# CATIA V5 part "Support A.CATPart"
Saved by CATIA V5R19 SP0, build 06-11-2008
Part number: Support A
Bounding box of the stored display mesh (mm): x -127 to 127, y -305.791 to 314.01, z -1400.007 to -1200.007
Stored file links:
  G:\EU_thinkMotion\CFAO_2010\MMS_groupe3\MMS_groupe3\rdalborgo\rdalborgo\Support A.CATPart
  G:\EU_thinkMotion\CFAO_2010\MMS_groupe3\MMS_groupe3\rdalborgo\rdalborgo\rdalborgo.CATProduct
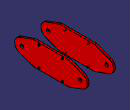
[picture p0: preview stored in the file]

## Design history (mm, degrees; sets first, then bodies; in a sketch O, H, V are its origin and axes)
External parameters (linked from other documents)
  External.entraxe = 500 mm
  `External.Largeur bielle` = 210 mm
Set1
  Plane1: linked copy from another document
  Point1 "C bielle": linked copy from another document
  Point2 "D bielle": linked copy from another document
  Line1: linked copy from another document
  Point3 "Axe sabot": linked copy from another document
  Plane2 to Plane4: linked copy from another document
Body1 (main body)
  Sketch1 on Plane1, origin (0, 0, 0), H (0, 1, 0), V (0, 0, 1)
    arc A1 centre (254.0096, -1300.0067) radius 60 from (314.0096, -1300.0067) to (274.4283, -1243.588) ccw
    point P1 (254.0096, -1300.0067)
    reference projected point E1 (254.0096, -1300.0067) from Point1
    point P2 (-245.9904, -1300.0067)
    reference projected point E2 (-245.9904, -1300.0067) from Point2
    point P3 (-145.9904, -1200.0067)
    line L1 (-145.9904, -1200.0067) -> (154.0096, -1200.0067)
    line L2 (154.0096, -1400.0067) -> (-145.9904, -1400.0067)
    point P4 (154.0096, -1200.0067)
    point P5 (154.0096, -1400.0067)
    reference projected point E3 (4.0096, -1300.0067) from Point3
    line L3 (154.0096, -1200.0067) -> (274.4283, -1243.588)
    line L4 (154.0096, -1400.0067) -> (274.4283, -1356.4254)
    point P8 (274.4283, -1356.4254)
    line L5 (-145.9904, -1400.0067) -> (-266.4092, -1356.4254)
    line L6 (-145.9904, -1200.0067) -> (-266.4092, -1243.588)
    reference projected line E4 (4.0096, -830) -> (4.0096, -1500) from Line1
    reference projected line E5 (4.0096, -830) -> (4.0096, -1500) from Line1
    arc A2 centre (254.0096, -1300.0067) radius 60 from (274.4283, -1356.4254) to (314.0096, -1300.0067) ccw
    point P11 (314.0096, -1300.0067)
    point P12 (314.0096, -1300.0067)
    arc A3 centre (-245.9904, -1300.0067) radius 60 from (-266.4092, -1243.588) to (-266.4092, -1356.4254) ccw
    circle A4 centre (-245.9904, -1300.0067) radius 15
    point P13 (-245.9904, -1300.0067)
    circle A5 centre (254.0096, -1300.0067) radius 15
    point P14 (254.0096, -1300.0067)
    reference projected point E6 (-245.9904, -1300.0067) from Point2
    reference projected point E7 (254.0096, -1300.0067) from Point1
    radius A1 = 60
    distance L1 L2 = 200
    distance L1 E3 = 100
    distance P4 P3 = 300 {= External.entraxe -200mm}
    distance P4 E4 = 150 {= (External.entraxe -200mm)/2}
    length L2 = 300 {= External.entraxe -200mm}
    distance P5 E5 = 150 {= (External.entraxe -200mm)/2}
    radius A3 = 60
    radius A4 = 15
    radius A5 = 15
    coincidence: P1 E1, P2 E2, P8 A1, A1 A2, P13 E6, P14 E7, P11 P12
    horizontal: L1 H, L2 H
    tangency: L3 A1, L4 A1, A3 L6, A3 L5
  Pad1: profile Sketch1, direction (1, 0, 0), length 120 {= `External.Largeur bielle`/2 +15mm}, opposite side length -105 {= -`External.Largeur bielle` /2}
  Sketch2 on end face of Pad1, origin (120, -139.9474, -1261.6138), H (0, 1, 0), V (0, 0, 1)
    point P1 (43.9569, 46.6071)
    reference projected line E1 (143.9569, 431.6138) -> (143.9569, -238.3862) from Line1
    reference intersected line E2 through (0, -38.3929) direction (-1, 0) from Plane2
    distance P1 E1 = 100
    distance P1 E2 = 85
  Hole1: placed by Sketch2, at (120, -95.9904, -1215.0067) direction (-1, 0, 0), diameter 10, through (limit type 6)
  RectPattern1: of Hole1, direction 1 instances 2, spacing 200, along Plane3, direction 2 instances 2, spacing 170, along Plane3 reversed
  Pad2: profile Sketch1, direction (-1, 0, 0), length 120 {= `External.Largeur bielle` /2+15mm}, opposite side length -105 {= -`External.Largeur bielle` /2}
  Sketch3 on end face of Pad2, origin (-120, -3.1951, -1265.3574), H (0, 1, 0), V (0, 0, -1)
    point P1 (107.2047, -50.3507)
    reference intersected line E1 through (7.2047, 0) direction (0, 1) from Plane4
    reference intersected line E2 through (0, 34.6493) direction (1, 0) from Plane2
    distance P1 E1 = 100
    distance P1 E2 = 85
  Hole2: placed by Sketch3, at (-120, 104.0096, -1215.0067) direction (1, 0, 0), diameter 10, through (limit type 6)
  RectPattern2: of Hole2, direction 1 instances 2, spacing 200, along Plane1 reversed, direction 2 instances 2, spacing 170, along Plane1 reversed
Body2 "Vis 10*30"
  Sketch4 on end face of Pad2, origin (-120, 0, 0), H (0, -1, 0), V (0, 0, 1)
    circle A1 centre (95.9904, -1215.0067) radius 5
    point P1 (95.9904, -1215.0067)
    reference projected circle E1 centre (95.9904, -1215.0067) radius 5 from edge [face of RectPattern2 | end face of Pad2]
    radius A1 = 5
    concentricity: P1 E1
  Pad3: profile Sketch4, direction (1, 0, 0), length 30
  Chamfer1: length 1, angle 45, on end face of Pad3
  Sketch5 on start face of Pad3, origin (-120, 0, 0), H (0, -1, 0), V (0, 0, 1)
    circle A1 centre (95.9904, -1215.0067) radius 7.5
    reference projected circle E1 centre (95.9904, -1215.0067) radius 5 from edge [face of RectPattern2 | end face of Pad2]
    radius A1 = 7.5
    concentricity: A1 E1
  Pad4: profile Sketch5, direction (-1, 0, 0), length 2
  Sketch6 on end face of Pad4, origin (-122, 0, 0), H (0, -1, 0), V (0, 0, 1)
    point P1 (95.9904, -1215.0067)
    point P2 (92.8192, -1220.5091)
    point P3 (99.17, -1220.5043)
    point P4 (102.3413, -1215.0019)
    point P5 (99.1617, -1209.5043)
    point P6 (92.8108, -1209.5091)
    point P7 (89.6396, -1215.0115)
    point P8 (95.9946, -1220.5067)
    line L1 (92.8192, -1220.5091) -> (99.17, -1220.5043)
    line L2 (99.17, -1220.5043) -> (102.3413, -1215.0019)
    line L3 (102.3413, -1215.0019) -> (99.1617, -1209.5043)
    line L4 (99.1617, -1209.5043) -> (92.8108, -1209.5091)
    line L5 (92.8108, -1209.5091) -> (89.6396, -1215.0115)
    line L6 (89.6396, -1215.0115) -> (92.8192, -1220.5091)
    construction line L7 (95.9904, -1215.0067) -> (95.9946, -1220.5067)
    construction circle A1 centre (95.9904, -1215.0067) radius 6.3509
    construction arc A2 centre (92.8108, -1209.5091) radius 6.3509 from (99.1617, -1209.5043) to (89.6396, -1215.0115) cw
    construction arc A3 centre (99.17, -1220.5043) radius 6.3509 from (102.3413, -1215.0019) to (92.8192, -1220.5091) ccw
    reference projected circle E1 centre (95.9904, -1215.0067) radius 7.5 from edge [face of Pad4 from Sketch5.A1 | end face of Pad4]
    distance L4 P8 = 11
    coincidence: A1 P2, A1 P3, A1 P4, A1 P5, A1 P6, A1 P7, A2 P1, A3 P1
    midpoint: P8 L1
    parallelism: L1 L4
    concentricity: P1 E1
  Pad5: profile Sketch6, direction (-1, 0, 0), length 5
Body3 "Vis 2"
  Sketch7 on end face of Pad2, origin (-120, 0, 0), H (0, -1, 0), V (0, 0, 1)
    circle A1 centre (-104.0096, -1215.0067) radius 5
    point P1 (-104.0096, -1215.0067)
    reference projected circle E1 centre (-104.0096, -1215.0067) radius 5 from edge [face of Hole2 | end face of Pad2]
    radius A1 = 5
    concentricity: P1 E1
  Pad6: profile Sketch7, direction (1, 0, 0), length 30
  Chamfer2: length 1, angle 45, on end face of Pad6
  Sketch8 on start face of Pad6, origin (-120, 0, 0), H (0, -1, 0), V (0, 0, 1)
    circle A1 centre (-104.0096, -1215.0067) radius 7.5
    reference projected circle E1 centre (-104.0096, -1215.0067) radius 5 from edge [face of Hole2 | end face of Pad2]
    radius A1 = 7.5
    concentricity: A1 E1
  Pad7: profile Sketch8, direction (-1, 0, 0), length 2
  Sketch9 on end face of Pad7, origin (-122, 0, 0), H (0, -1, 0), V (0, 0, 1)
    point P1 (-104.0096, -1215.0067)
    point P2 (-107.1808, -1220.5091)
    point P3 (-100.83, -1220.5043)
    point P4 (-97.6587, -1215.0019)
    point P5 (-100.8383, -1209.5043)
    point P6 (-107.1892, -1209.5091)
    point P7 (-110.3604, -1215.0115)
    point P8 (-104.0054, -1220.5067)
    line L1 (-107.1808, -1220.5091) -> (-100.83, -1220.5043)
    line L2 (-100.83, -1220.5043) -> (-97.6587, -1215.0019)
    line L3 (-97.6587, -1215.0019) -> (-100.8383, -1209.5043)
    line L4 (-100.8383, -1209.5043) -> (-107.1892, -1209.5091)
    line L5 (-107.1892, -1209.5091) -> (-110.3604, -1215.0115)
    line L6 (-110.3604, -1215.0115) -> (-107.1808, -1220.5091)
    construction line L7 (-104.0096, -1215.0067) -> (-104.0054, -1220.5067)
    construction circle A1 centre (-104.0096, -1215.0067) radius 6.3509
    construction arc A2 centre (-107.1892, -1209.5091) radius 6.3509 from (-100.8383, -1209.5043) to (-110.3604, -1215.0115) cw
    construction arc A3 centre (-100.83, -1220.5043) radius 6.3509 from (-97.6587, -1215.0019) to (-107.1808, -1220.5091) ccw
    reference projected circle E1 centre (-104.0096, -1215.0067) radius 7.5 from edge [face of Pad7 from Sketch8.A1 | end face of Pad7]
    distance L4 P8 = 11
    coincidence: A1 P2, A1 P3, A1 P4, A1 P5, A1 P6, A1 P7, A2 P1, A3 P1
    midpoint: P8 L1
    parallelism: L1 L4
    concentricity: P1 E1
  Pad8: profile Sketch9, direction (-1, 0, 0), length 5
Body4 "Vis 3"
  Sketch10 on end face of Pad2, origin (-120, 0, 0), H (0, -1, 0), V (0, 0, 1)
    circle A1 centre (-104.0096, -1385.0067) radius 5
    point P1 (-104.0096, -1385.0067)
    reference projected circle E1 centre (-104.0096, -1385.0067) radius 5 from edge [face of RectPattern2 | end face of Pad2]
    radius A1 = 5
    concentricity: P1 E1
  Pad9: profile Sketch10, direction (1, 0, 0), length 30
  Chamfer3: length 1, angle 45, on end face of Pad9
  Sketch11 on start face of Pad9, origin (-120, 0, 0), H (0, -1, 0), V (0, 0, 1)
    circle A1 centre (-104.0096, -1385.0067) radius 7.5
    reference projected circle E1 centre (-104.0096, -1385.0067) radius 5 from edge [face of RectPattern2 | end face of Pad2]
    radius A1 = 7.5
    concentricity: A1 E1
  Pad10: profile Sketch11, direction (-1, 0, 0), length 2
  Sketch12 on end face of Pad10, origin (-122, 0, 0), H (0, -1, 0), V (0, 0, 1)
    point P1 (-104.0096, -1385.0067)
    point P2 (-107.1808, -1390.5091)
    point P3 (-100.83, -1390.5043)
    point P4 (-97.6587, -1385.0019)
    point P5 (-100.8383, -1379.5043)
    point P6 (-107.1892, -1379.5091)
    point P7 (-110.3604, -1385.0115)
    point P8 (-104.0054, -1390.5067)
    line L1 (-107.1808, -1390.5091) -> (-100.83, -1390.5043)
    line L2 (-100.83, -1390.5043) -> (-97.6587, -1385.0019)
    line L3 (-97.6587, -1385.0019) -> (-100.8383, -1379.5043)
    line L4 (-100.8383, -1379.5043) -> (-107.1892, -1379.5091)
    line L5 (-107.1892, -1379.5091) -> (-110.3604, -1385.0115)
    line L6 (-110.3604, -1385.0115) -> (-107.1808, -1390.5091)
    construction line L7 (-104.0096, -1385.0067) -> (-104.0054, -1390.5067)
    construction circle A1 centre (-104.0096, -1385.0067) radius 6.3509
    construction arc A2 centre (-107.1892, -1379.5091) radius 6.3509 from (-100.8383, -1379.5043) to (-110.3604, -1385.0115) cw
    construction arc A3 centre (-100.83, -1390.5043) radius 6.3509 from (-97.6587, -1385.0019) to (-107.1808, -1390.5091) ccw
    reference projected circle E1 centre (-104.0096, -1385.0067) radius 7.5 from edge [face of Pad10 from Sketch11.A1 | end face of Pad10]
    distance L4 P8 = 11
    coincidence: A1 P2, A1 P3, A1 P4, A1 P5, A1 P6, A1 P7, A2 P1, A3 P1
    midpoint: P8 L1
    parallelism: L1 L4
    concentricity: P1 E1
  Pad11: profile Sketch12, direction (-1, 0, 0), length 5
Body5 "Vis 4"
  Sketch13 on end face of Pad2, origin (-120, 0, 0), H (0, -1, 0), V (0, 0, 1)
    circle A1 centre (95.9904, -1385.0067) radius 5
    point P1 (95.9904, -1385.0067)
    reference projected circle E1 centre (95.9904, -1385.0067) radius 5 from edge [face of RectPattern2 | end face of Pad2]
    radius A1 = 5
    concentricity: P1 E1
  Pad12: profile Sketch13, direction (1, 0, 0), length 30
  Chamfer4: length 1, angle 45, on end face of Pad12
  Sketch14 on start face of Pad12, origin (-120, 0, 0), H (0, -1, 0), V (0, 0, 1)
    circle A1 centre (95.9904, -1385.0067) radius 7.5
    reference projected circle E1 centre (95.9904, -1385.0067) radius 5 from edge [face of RectPattern2 | end face of Pad2]
    radius A1 = 7.5
    concentricity: A1 E1
  Pad13: profile Sketch14, direction (-1, 0, 0), length 2
  Sketch15 on end face of Pad13, origin (-122, 0, 0), H (0, -1, 0), V (0, 0, 1)
    point P1 (95.9904, -1385.0067)
    point P2 (92.8192, -1390.5091)
    point P3 (99.17, -1390.5043)
    point P4 (102.3413, -1385.0019)
    point P5 (99.1617, -1379.5043)
    point P6 (92.8108, -1379.5091)
    point P7 (89.6396, -1385.0115)
    point P8 (95.9946, -1390.5067)
    line L1 (92.8192, -1390.5091) -> (99.17, -1390.5043)
    line L2 (99.17, -1390.5043) -> (102.3413, -1385.0019)
    line L3 (102.3413, -1385.0019) -> (99.1617, -1379.5043)
    line L4 (99.1617, -1379.5043) -> (92.8108, -1379.5091)
    line L5 (92.8108, -1379.5091) -> (89.6396, -1385.0115)
    line L6 (89.6396, -1385.0115) -> (92.8192, -1390.5091)
    construction line L7 (95.9904, -1385.0067) -> (95.9946, -1390.5067)
    construction circle A1 centre (95.9904, -1385.0067) radius 6.3509
    construction arc A2 centre (92.8108, -1379.5091) radius 6.3509 from (99.1617, -1379.5043) to (89.6396, -1385.0115) cw
    construction arc A3 centre (99.17, -1390.5043) radius 6.3509 from (102.3413, -1385.0019) to (92.8192, -1390.5091) ccw
    reference projected circle E1 centre (95.9904, -1385.0067) radius 7.5 from edge [face of Pad13 from Sketch14.A1 | end face of Pad13]
    distance L4 P8 = 11
    coincidence: A1 P2, A1 P3, A1 P4, A1 P5, A1 P6, A1 P7, A2 P1, A3 P1
    midpoint: P8 L1
    parallelism: L1 L4
    concentricity: P1 E1
  Pad14: profile Sketch15, direction (-1, 0, 0), length 5
Body6 "Vis 5"
  Sketch16 on end face of Pad1, origin (120, 0, 0), H (0, 1, 0), V (0, 0, 1)
    circle A1 centre (-95.9904, -1215.0067) radius 5
    point P1 (-95.9904, -1215.0067)
    reference projected circle E1 centre (-95.9904, -1215.0067) radius 5 from edge [end face of Pad1 | face of Hole1]
    radius A1 = 5
    concentricity: P1 E1
  Pad15: profile Sketch16, direction (-1, 0, 0), length 30
  Chamfer5: length 1, angle 45, on end face of Pad15
  Sketch17 on start face of Pad15, origin (120, 0, 0), H (0, 1, 0), V (0, 0, 1)
    circle A1 centre (-95.9904, -1215.0067) radius 7.5
    reference projected circle E1 centre (-95.9904, -1215.0067) radius 5 from edge [end face of Pad1 | face of Hole1]
    radius A1 = 7.5
    concentricity: A1 E1
  Pad16: profile Sketch17, direction (1, 0, 0), length 2
  Sketch18 on end face of Pad16, origin (122, 0, 0), H (0, 1, 0), V (0, 0, 1)
    point P1 (-95.9904, -1215.0067)
    point P2 (-99.1617, -1220.5091)
    point P3 (-92.8108, -1220.5043)
    point P4 (-89.6396, -1215.0019)
    point P5 (-92.8192, -1209.5043)
    point P6 (-99.17, -1209.5091)
    point P7 (-102.3413, -1215.0115)
    point P8 (-95.9863, -1220.5067)
    line L1 (-99.1617, -1220.5091) -> (-92.8108, -1220.5043)
    line L2 (-92.8108, -1220.5043) -> (-89.6396, -1215.0019)
    line L3 (-89.6396, -1215.0019) -> (-92.8192, -1209.5043)
    line L4 (-92.8192, -1209.5043) -> (-99.17, -1209.5091)
    line L5 (-99.17, -1209.5091) -> (-102.3413, -1215.0115)
    line L6 (-102.3413, -1215.0115) -> (-99.1617, -1220.5091)
    construction line L7 (-95.9904, -1215.0067) -> (-95.9863, -1220.5067)
    construction circle A1 centre (-95.9904, -1215.0067) radius 6.3509
    construction arc A2 centre (-99.17, -1209.5091) radius 6.3509 from (-92.8192, -1209.5043) to (-102.3413, -1215.0115) cw
    construction arc A3 centre (-92.8108, -1220.5043) radius 6.3509 from (-89.6396, -1215.0019) to (-99.1617, -1220.5091) ccw
    reference projected circle E1 centre (-95.9904, -1215.0067) radius 7.5 from edge [face of Pad16 from Sketch17.A1 | end face of Pad16]
    distance L4 P8 = 11
    coincidence: A1 P2, A1 P3, A1 P4, A1 P5, A1 P6, A1 P7, A2 P1, A3 P1
    midpoint: P8 L1
    parallelism: L1 L4
    concentricity: P1 E1
  Pad17: profile Sketch18, direction (1, 0, 0), length 5
Body7 "Vis 6"
  Sketch19 on end face of Pad1, origin (120, 0, 0), H (0, 1, 0), V (0, 0, 1)
    circle A1 centre (104.0096, -1215.0067) radius 5
    point P1 (104.0096, -1215.0067)
    reference projected circle E1 centre (104.0096, -1215.0067) radius 5 from edge [end face of Pad1 | face of RectPattern1]
    radius A1 = 5
    concentricity: P1 E1
  Pad18: profile Sketch19, direction (-1, 0, 0), length 30
  Chamfer6: length 1, angle 45, on end face of Pad18
  Sketch20 on start face of Pad18, origin (120, 0, 0), H (0, 1, 0), V (0, 0, 1)
    circle A1 centre (104.0096, -1215.0067) radius 7.5
    reference projected circle E1 centre (104.0096, -1215.0067) radius 5 from edge [end face of Pad1 | face of RectPattern1]
    radius A1 = 7.5
    concentricity: A1 E1
  Pad19: profile Sketch20, direction (1, 0, 0), length 2
  Sketch21 on end face of Pad19, origin (122, 0, 0), H (0, 1, 0), V (0, 0, 1)
    point P1 (104.0096, -1215.0067)
    point P2 (100.8383, -1220.5091)
    point P3 (107.1892, -1220.5043)
    point P4 (110.3604, -1215.0019)
    point P5 (107.1808, -1209.5043)
    point P6 (100.83, -1209.5091)
    point P7 (97.6587, -1215.0115)
    point P8 (104.0137, -1220.5067)
    line L1 (100.8383, -1220.5091) -> (107.1892, -1220.5043)
    line L2 (107.1892, -1220.5043) -> (110.3604, -1215.0019)
    line L3 (110.3604, -1215.0019) -> (107.1808, -1209.5043)
    line L4 (107.1808, -1209.5043) -> (100.83, -1209.5091)
    line L5 (100.83, -1209.5091) -> (97.6587, -1215.0115)
    line L6 (97.6587, -1215.0115) -> (100.8383, -1220.5091)
    construction line L7 (104.0096, -1215.0067) -> (104.0137, -1220.5067)
    construction circle A1 centre (104.0096, -1215.0067) radius 6.3509
    construction arc A2 centre (100.83, -1209.5091) radius 6.3509 from (107.1808, -1209.5043) to (97.6587, -1215.0115) cw
    construction arc A3 centre (107.1892, -1220.5043) radius 6.3509 from (110.3604, -1215.0019) to (100.8383, -1220.5091) ccw
    reference projected circle E1 centre (104.0096, -1215.0067) radius 7.5 from edge [face of Pad19 from Sketch20.A1 | end face of Pad19]
    distance L4 P8 = 11
    coincidence: A1 P2, A1 P3, A1 P4, A1 P5, A1 P6, A1 P7, A2 P1, A3 P1
    midpoint: P8 L1
    parallelism: L1 L4
    concentricity: P1 E1
  Pad20: profile Sketch21, direction (1, 0, 0), length 5
Body8 "Vis 7"
  Sketch22 on end face of Pad1, origin (120, 0, 0), H (0, 1, 0), V (0, 0, 1)
    circle A1 centre (104.0096, -1385.0067) radius 5
    point P1 (104.0096, -1385.0067)
    reference projected circle E1 centre (104.0096, -1385.0067) radius 5 from edge [end face of Pad1 | face of RectPattern1]
    radius A1 = 5
    concentricity: P1 E1
  Pad21: profile Sketch22, direction (-1, 0, 0), length 30
  Chamfer7: length 1, angle 45, on end face of Pad21
  Sketch23 on start face of Pad21, origin (120, 0, 0), H (0, 1, 0), V (0, 0, 1)
    circle A1 centre (104.0096, -1385.0067) radius 7.5
    reference projected circle E1 centre (104.0096, -1385.0067) radius 5 from edge [end face of Pad1 | face of RectPattern1]
    radius A1 = 7.5
    concentricity: A1 E1
  Pad22: profile Sketch23, direction (1, 0, 0), length 2
  Sketch24 on end face of Pad22, origin (122, 0, 0), H (0, 1, 0), V (0, 0, 1)
    point P1 (104.0096, -1385.0067)
    point P2 (100.8383, -1390.5091)
    point P3 (107.1892, -1390.5043)
    point P4 (110.3604, -1385.0019)
    point P5 (107.1808, -1379.5043)
    point P6 (100.83, -1379.5091)
    point P7 (97.6587, -1385.0115)
    point P8 (104.0137, -1390.5067)
    line L1 (100.8383, -1390.5091) -> (107.1892, -1390.5043)
    line L2 (107.1892, -1390.5043) -> (110.3604, -1385.0019)
    line L3 (110.3604, -1385.0019) -> (107.1808, -1379.5043)
    line L4 (107.1808, -1379.5043) -> (100.83, -1379.5091)
    line L5 (100.83, -1379.5091) -> (97.6587, -1385.0115)
    line L6 (97.6587, -1385.0115) -> (100.8383, -1390.5091)
    construction line L7 (104.0096, -1385.0067) -> (104.0137, -1390.5067)
    construction circle A1 centre (104.0096, -1385.0067) radius 6.3509
    construction arc A2 centre (100.83, -1379.5091) radius 6.3509 from (107.1808, -1379.5043) to (97.6587, -1385.0115) cw
    construction arc A3 centre (107.1892, -1390.5043) radius 6.3509 from (110.3604, -1385.0019) to (100.8383, -1390.5091) ccw
    reference projected circle E1 centre (104.0096, -1385.0067) radius 7.5 from edge [face of Pad22 from Sketch23.A1 | end face of Pad22]
    distance L4 P8 = 11
    coincidence: A1 P2, A1 P3, A1 P4, A1 P5, A1 P6, A1 P7, A2 P1, A3 P1
    midpoint: P8 L1
    parallelism: L1 L4
    concentricity: P1 E1
  Pad23: profile Sketch24, direction (1, 0, 0), length 5
Body9 "Vis 8"
  Sketch25 on end face of Pad1, origin (120, 0, 0), H (0, 1, 0), V (0, 0, 1)
    circle A1 centre (-95.9904, -1385.0067) radius 5
    point P1 (-95.9904, -1385.0067)
    reference projected circle E1 centre (-95.9904, -1385.0067) radius 5 from edge [end face of Pad1 | face of RectPattern1]
    radius A1 = 5
    concentricity: P1 E1
  Pad24: profile Sketch25, direction (-1, 0, 0), length 30
  Chamfer8: length 1, angle 45, on end face of Pad24
  Sketch26 on start face of Pad24, origin (120, 0, 0), H (0, 1, 0), V (0, 0, 1)
    circle A1 centre (-95.9904, -1385.0067) radius 7.5
    reference projected circle E1 centre (-95.9904, -1385.0067) radius 5 from edge [end face of Pad1 | face of RectPattern1]
    radius A1 = 7.5
    concentricity: A1 E1
  Pad25: profile Sketch26, direction (1, 0, 0), length 2
  Sketch27 on end face of Pad25, origin (122, 0, 0), H (0, 1, 0), V (0, 0, 1)
    point P1 (-95.9904, -1385.0067)
    point P2 (-99.1617, -1390.5091)
    point P3 (-92.8108, -1390.5043)
    point P4 (-89.6396, -1385.0019)
    point P5 (-92.8192, -1379.5043)
    point P6 (-99.17, -1379.5091)
    point P7 (-102.3413, -1385.0115)
    point P8 (-95.9863, -1390.5067)
    line L1 (-99.1617, -1390.5091) -> (-92.8108, -1390.5043)
    line L2 (-92.8108, -1390.5043) -> (-89.6396, -1385.0019)
    line L3 (-89.6396, -1385.0019) -> (-92.8192, -1379.5043)
    line L4 (-92.8192, -1379.5043) -> (-99.17, -1379.5091)
    line L5 (-99.17, -1379.5091) -> (-102.3413, -1385.0115)
    line L6 (-102.3413, -1385.0115) -> (-99.1617, -1390.5091)
    construction line L7 (-95.9904, -1385.0067) -> (-95.9863, -1390.5067)
    construction circle A1 centre (-95.9904, -1385.0067) radius 6.3509
    construction arc A2 centre (-99.17, -1379.5091) radius 6.3509 from (-92.8192, -1379.5043) to (-102.3413, -1385.0115) cw
    construction arc A3 centre (-92.8108, -1390.5043) radius 6.3509 from (-89.6396, -1385.0019) to (-99.1617, -1390.5091) ccw
    reference projected circle E1 centre (-95.9904, -1385.0067) radius 7.5 from edge [face of Pad25 from Sketch26.A1 | end face of Pad25]
    distance L4 P8 = 11
    coincidence: A1 P2, A1 P3, A1 P4, A1 P5, A1 P6, A1 P7, A2 P1, A3 P1
    midpoint: P8 L1
    parallelism: L1 L4
    concentricity: P1 E1
  Pad26: profile Sketch27, direction (1, 0, 0), length 5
